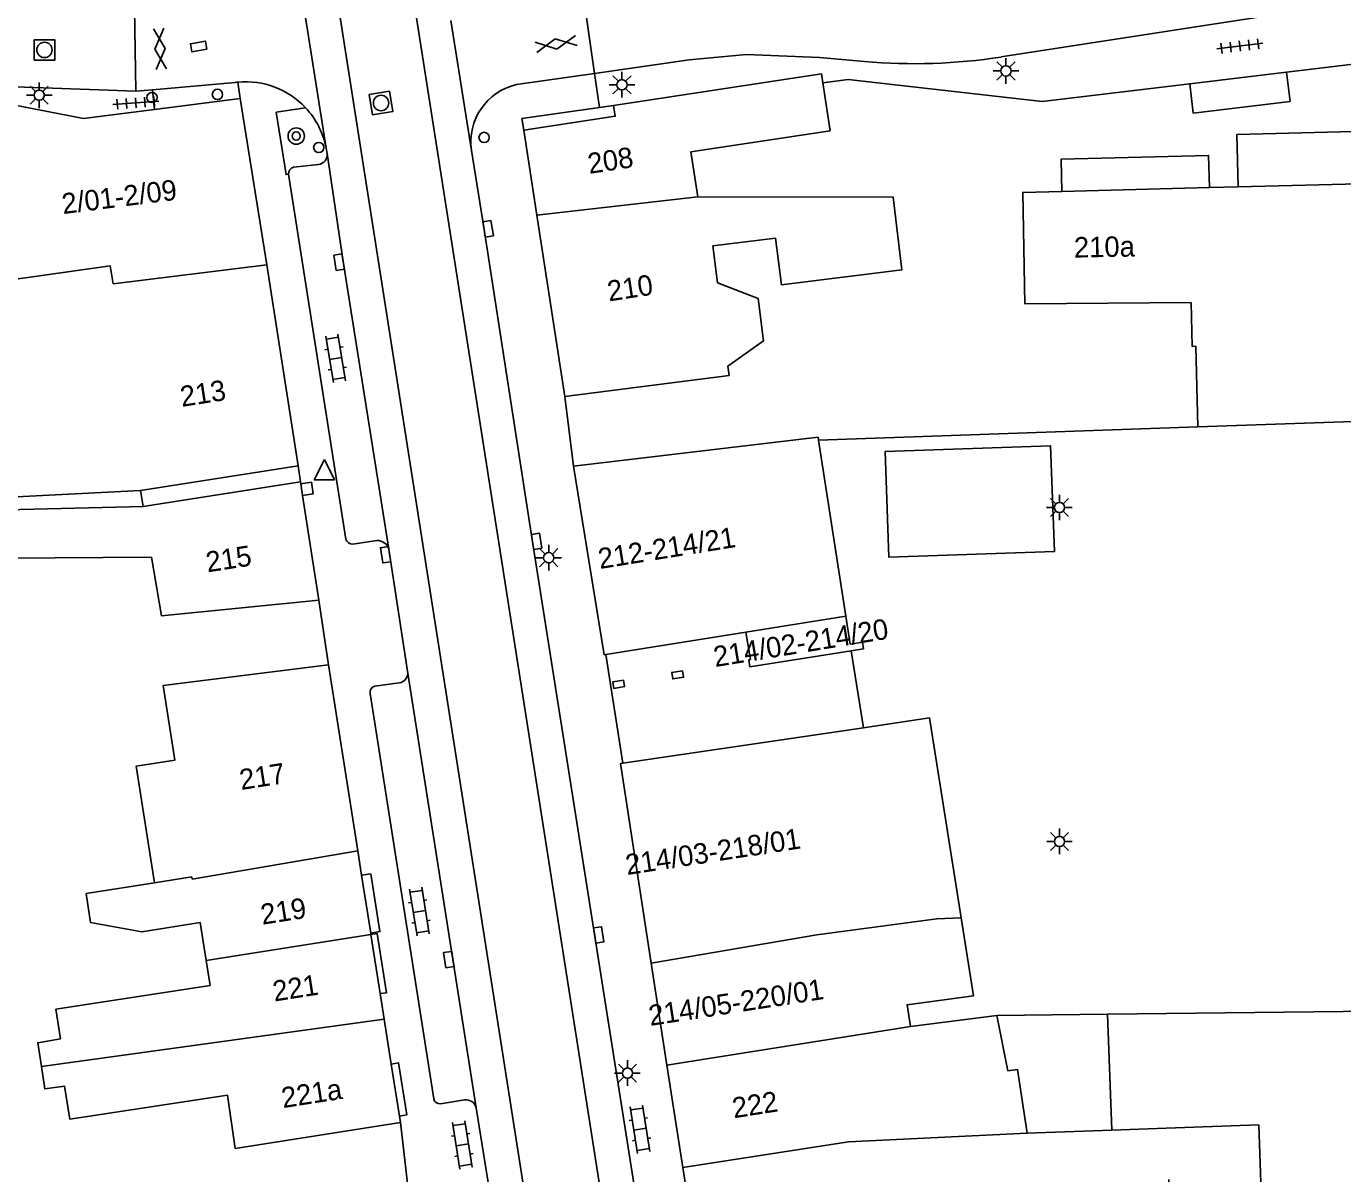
# Model space of a CAD drawing. Extents: x 132998 to 136004, y 396998 to 398512.
# Drawn here: x 133249 to 133313.3, y 397948.6 to 398004.6 of the extents above; entities that cross this region are included whole.
import ezdxf

# ---------------------------------------------------------------- set-up
doc = ezdxf.new("R2010")
doc.units = 0
for name, color, linetype in [('gg-afsc-muur', 7, 'Continuous'), ('gg-anno-huisnummerreeks BGT', 7, 'Continuous'), ('gg-bbg-gedigitaliseerde bebouwing', 7, 'Continuous'), ('gg-bbg-gedigitaliseerde bebouwing onder overbouw', 7, 'Continuous'), ('gg-bbg-gedigitaliseerde overbouw', 7, 'Continuous'), ('gg-bbg-hoofdgebouw', 7, 'Continuous'), ('gg-bbg-luifel en loopbrug', 7, 'Continuous'), ('gg-bbg-onder overbouw', 7, 'Continuous'), ('gg-bbg-overig bouwwerk', 7, 'Continuous'), ('gg-bbg-pand overbouw', 7, 'Continuous'), ('gg-bbg-pilaar onder overbouw', 7, 'Continuous'), ('gg-bbg-tussenscheiding', 7, 'Continuous'), ('gg-knt-verharding', 7, 'Continuous'), ('gg-knt-verharding nz', 7, 'Continuous'), ('gt-grn-weggrens', 7, 'Continuous'), ('gt-symb-boom', 7, 'Continuous'), ('gt-symb-drukknoppaal', 7, 'Continuous'), ('gt-symb-gesloten verharding', 7, 'Continuous'), ('gt-symb-klinker verharding', 7, 'Continuous'), ('gt-symb-kolk', 7, 'Continuous'), ('gt-symb-kolk center center', 7, 'Continuous'), ('gt-symb-lichtmast', 7, 'Continuous'), ('gt-symb-rioolschacht', 7, 'Continuous'), ('gt-symb-tegel verharding', 7, 'Continuous'), ('gt-symb-verkeersregelinstallatiepaal', 7, 'Continuous'), ('gt-symb-waterafsluiter', 7, 'Continuous')]:
    doc.layers.add(name, color=color, linetype=linetype)

# ---------------------------------------------------------------- blocks, each defined once
blk = doc.blocks.new('gt0-RS')
at = {"layer": 'gt-symb-rioolschacht'}
blk.add_lwpolyline([(-0.5, -0.5), (0.5, -0.5), (0.5, 0.5), (-0.5, 0.5)], close=True, dxfattribs=at)
blk.add_circle((0, 0), 0.375, dxfattribs=at)
blk = doc.blocks.new('gt0-GESVH1')
at = {"layer": 'gt-symb-gesloten verharding'}
for p, q in [((-0.992, -0.261), (0.008, 0.239)), ((0.008, -0.261), (-0.992, 0.239)), ((0.008, 0.239), (1.008, -0.261)), ((1.008, 0.239), (0.008, -0.261))]:
    blk.add_line(p, q, dxfattribs=at)
blk = doc.blocks.new('gt0-TEG1')
at = {"layer": 'gt-symb-tegel verharding'}
for p, q in [((-1.125, 0), (1.125, 0)), ((-0.9, -0.25), (-0.9, 0.25)), ((-0.45, -0.25), (-0.45, 0.25)), ((0, -0.25), (0, 0.25)), ((0.45, -0.25), (0.45, 0.25)), ((0.9, -0.25), (0.9, 0.25))]:
    blk.add_line(p, q, dxfattribs=at)
blk = doc.blocks.new('gt0-LMAST')
at = {"layer": 'gt-symb-lichtmast'}
for p, q in [((-0.182, 0.173), (-0.447, 0.438)), ((-0.005, 0.246), (-0.005, 0.621)), ((0.172, 0.173), (0.437, 0.438)), ((-0.255, -0.004), (-0.63, -0.004)), ((-0.182, -0.181), (-0.447, -0.446)), ((-0.005, -0.254), (-0.005, -0.629)), ((0.437, -0.446), (0.172, -0.181)), ((0.245, -0.004), (0.62, -0.004))]:
    blk.add_line(p, q, dxfattribs=at)
blk.add_circle((-0.005, -0.004), 0.25, dxfattribs=at)
blk = doc.blocks.new('gt0-KOLK')
at = {"layer": 'gt-symb-kolk'}
blk.add_lwpolyline([(0, 0), (0.375, 0), (0.375, 0.4), (-0.375, 0.4), (-0.375, 0), (0, 0)], dxfattribs=at)
blk = doc.blocks.new('gt0-KL1')
at = {"layer": 'gt-symb-klinker verharding'}
for p, q in [((-1.15, 0.3), (1.15, 0.3)), ((-1, -0.3), (-1, 0.3)), ((-0.5, 0.3), (-0.5, 0.45)), ((0, -0.3), (0, 0.3)), ((0.5, 0.3), (0.5, 0.45)), ((1, -0.3), (1, 0.3)), ((-1.15, -0.3), (1.15, -0.3)), ((-0.5, -0.45), (-0.5, -0.3)), ((0.5, -0.45), (0.5, -0.3))]:
    blk.add_line(p, q, dxfattribs=at)
blk = doc.blocks.new('gt0-WAFSL')
at = {"layer": 'gt-symb-waterafsluiter'}
for p, q in [((-0.5, -0.333), (0, 0.667)), ((0, 0.667), (0.5, -0.333)), ((0.5, -0.333), (-0.5, -0.333))]:
    blk.add_line(p, q, dxfattribs=at)
blk = doc.blocks.new('gt0-VIPAAL')
at = {"layer": 'gt-symb-verkeersregelinstallatiepaal'}
blk.add_circle((0, 0), 0.25, dxfattribs=at)
blk = doc.blocks.new('gt0-BOOM')
at = {"layer": 'gt-symb-boom'}
for radius in [0.4, 0.2]:
    blk.add_circle((0, 0), radius, dxfattribs=at)
blk = doc.blocks.new('gt0-KOLKCC')
at = {"layer": 'gt-symb-kolk center center'}
blk.add_lwpolyline([(-0.375, 0.2), (0.375, 0.2), (0.375, -0.2), (-0.375, -0.2)], close=True, dxfattribs=at)
blk = doc.blocks.new('gt0-DPAAL')
at = {"layer": 'gt-symb-drukknoppaal'}
blk.add_circle((0, 0), 0.25, dxfattribs=at)

msp = doc.modelspace()

# ---------------------------------------------------------------- linework, layer by layer
at = {"layer": 'gg-afsc-muur'}
for p, q in [((133310.547, 398002.362), (133314.62, 398002.851)), ((133306.217, 397985.057), (133287.694, 397984.412)), ((133319.735, 397956.616), (133301.812, 397956.397))]:
    msp.add_line(p, q, dxfattribs=at)
msp.add_lwpolyline([(133287.915, 398001.851), (133289.14, 398002.001), (133298.62, 398000.931), (133305.823, 398001.795)], dxfattribs=at)
at = {"layer": 'gg-bbg-gedigitaliseerde bebouwing'}
for p, q in [((133238.066, 397981.119), (133254.599, 397981.955)), ((133248.053, 397981.01), (133254.722, 397981.169)), ((133297.882, 397950.596), (133302.013, 397950.743)), ((133302.013, 397950.743), (133304.675, 397950.837))]:
    msp.add_line(p, q, dxfattribs=at)
for points in [[(133281.81, 397996.285), (133281.467, 397998.477), (133288.27, 397999.51)], [(133285.883, 397991.993), (133291.766, 397992.724), (133291.343, 397996.263), (133281.81, 397996.285)], [(133263.31, 397976.6), (133255.618, 397975.843), (133255.14, 397978.696), (133248.078, 397978.649), (133248.053, 397981.01)], [(133263.78, 397973.45), (133255.697, 397972.447), (133256.074, 397970.051)], [(133256.074, 397970.051), (133256.272, 397968.793), (133254.378, 397968.495), (133255.274, 397962.81)], [(133254.669, 397960.421), (133252.163, 397960.882), (133251.942, 397962.287), (133255.274, 397962.81)], [(133257.805, 397959.028), (133257.516, 397960.868), (133254.669, 397960.421)], [(133249.76, 397953.846), (133249.583, 397955.006), (133250.685, 397955.197), (133250.463, 397956.64), (133257.997, 397957.803), (133257.805, 397959.028)], [(133297.882, 397950.596), (133297.414, 397953.702), (133296.947, 397953.632), (133296.41, 397956.331)], [(133267.29, 397951.11), (133259.225, 397949.855), (133258.846, 397952.444), (133251.147, 397951.284), (133250.893, 397952.888), (133249.926, 397952.755), (133249.76, 397953.846)], [(133304.675, 397950.837), (133309.191, 397950.998), (133309.324, 397947.268), (133304.843, 397947.108), (133304.799, 397948.341)]]:
    msp.add_lwpolyline(points, dxfattribs=at)
at = {"layer": 'gg-bbg-gedigitaliseerde bebouwing onder overbouw'}
for p, q in [((133262.287, 397983.156), (133254.599, 397981.955)), ((133254.722, 397981.169), (133262.409, 397982.37))]:
    msp.add_line(p, q, dxfattribs=at)
at = {"layer": 'gg-bbg-gedigitaliseerde overbouw'}
msp.add_line((133254.722, 397981.169), (133254.599, 397981.955), dxfattribs=at)
at = {"layer": 'gg-bbg-hoofdgebouw'}
for p, q in [((133287.915, 398001.851), (133288.27, 397999.51)), ((133259.455, 398001.074), (133255.281, 398000.542)), ((133260.768, 397992.966), (133259.455, 398001.074)), ((133273.95, 397995.384), (133273.31, 397999.53)), ((133299.58, 397996.55), (133306.778, 397996.736)), ((133306.778, 397996.736), (133308.191, 397996.772)), ((133308.191, 397996.772), (133315.45, 397996.96)), ((133275.315, 397986.545), (133273.95, 397995.384)), ((133262.287, 397983.156), (133260.768, 397992.966)), ((133306.217, 397985.057), (133317.351, 397985.444)), ((133289.026, 397975.816), (133287.694, 397984.412)), ((133262.423, 397982.282), (133262.409, 397982.37)), ((133262.512, 397981.71), (133262.423, 397982.282)), ((133263.31, 397976.6), (133262.512, 397981.71)), ((133289.236, 397974.461), (133289.026, 397975.816)), ((133263.78, 397973.45), (133265.206, 397964.371)), ((133265.206, 397964.371), (133265.393, 397963.183)), ((133265.393, 397963.183), (133265.837, 397960.357)), ((133265.837, 397960.357), (133265.847, 397960.292)), ((133265.847, 397960.292), (133265.848, 397960.288)), ((133265.848, 397960.288), (133266.301, 397957.403)), ((133279.524, 397958.887), (133280.292, 397953.914)), ((133266.301, 397957.403), (133266.496, 397956.164)), ((133292.19, 397955.797), (133296.41, 397956.331)), ((133266.496, 397956.164), (133266.841, 397953.965)), ((133266.841, 397953.965), (133267.24, 397951.426)), ((133280.292, 397953.914), (133281.072, 397948.926)), ((133267.24, 397951.426), (133267.29, 397951.11)), ((133281.072, 397948.926), (133282.056, 397942.566))]:
    msp.add_line(p, q, dxfattribs=at)
for points in [[(133287.915, 398001.851), (133287.85, 398002.281), (133277.69, 398000.741)], [(133255.281, 398000.542), (133251.821, 398000.101), (133246.681, 398001.094), (133246.587, 398001.061)], [(133273.31, 397999.53), (133277.77, 398000.211), (133277.69, 398000.741)], [(133305.892, 397991.125), (133297.772, 397991.059), (133297.67, 397996.501), (133299.58, 397996.55)], [(133285.883, 397991.993), (133285.601, 397994.266), (133282.544, 397993.886), (133282.767, 397992.09), (133284.747, 397991.318), (133285.004, 397989.254), (133283.271, 397988.021), (133283.329, 397987.565), (133275.315, 397986.545)], [(133306.217, 397985.057), (133306.125, 397988.99), (133305.932, 397988.986), (133305.892, 397991.125)], [(133287.694, 397984.412), (133287.672, 397984.555), (133275.74, 397983.135)], [(133275.74, 397983.135), (133277.233, 397973.94), (133277.32, 397973.954)], [(133289.287, 397974.131), (133289.893, 397974.23), (133289.842, 397974.555), (133289.236, 397974.461)], [(133289.893, 397970.377), (133293.117, 397970.856), (133294.66, 397961.098)], [(133279.524, 397958.887), (133278.027, 397968.626), (133278.137, 397968.642)], [(133294.66, 397961.098), (133295.261, 397957.294), (133292.021, 397956.863), (133292.19, 397955.797)]]:
    msp.add_lwpolyline(points, dxfattribs=at)
at = {"layer": 'gg-bbg-luifel en loopbrug'}
for p, q in [((133305.823, 398001.795), (133310.547, 398002.362)), ((133301.812, 397956.397), (133296.41, 397956.331)), ((133302.013, 397950.743), (133301.812, 397956.397))]:
    msp.add_line(p, q, dxfattribs=at)
for points in [[(133305.823, 398001.795), (133305.995, 398000.363), (133310.719, 398000.93), (133310.547, 398002.362)], [(133315.092, 397999.503), (133308.125, 397999.323), (133308.191, 397996.772)], [(133306.778, 397996.736), (133306.737, 397998.306), (133299.539, 397998.12), (133299.58, 397996.55)]]:
    msp.add_lwpolyline(points, dxfattribs=at)
at = {"layer": 'gg-bbg-onder overbouw'}
for p, q in [((133277.32, 397973.954), (133284.153, 397975.037)), ((133278.137, 397968.642), (133289.893, 397970.377))]:
    msp.add_line(p, q, dxfattribs=at)
msp.add_lwpolyline([(133289.287, 397974.131), (133284.348, 397973.35), (133284.289, 397973.691), (133284.371, 397973.704), (133284.153, 397975.037)], dxfattribs=at)
at = {"layer": 'gg-bbg-overig bouwwerk'}
msp.add_lwpolyline([(133299.21, 397978.985), (133299.03, 397984.135), (133290.943, 397983.853), (133291.122, 397978.703), (133299.21, 397978.985)], dxfattribs=at)
at = {"layer": 'gg-bbg-pand overbouw'}
for p, q in [((133262.409, 397982.37), (133262.287, 397983.156)), ((133278.137, 397968.642), (133277.32, 397973.954)), ((133289.287, 397974.131), (133289.893, 397970.377))]:
    msp.add_line(p, q, dxfattribs=at)
at = {"layer": 'gg-bbg-pilaar onder overbouw'}
for points in [[(133281.056, 397973.158), (133281.107, 397972.842), (133280.578, 397972.758), (133280.528, 397973.074), (133281.056, 397973.158)], [(133278.176, 397972.699), (133278.226, 397972.383), (133277.698, 397972.299), (133277.648, 397972.615), (133278.176, 397972.699)]]:
    msp.add_lwpolyline(points, dxfattribs=at)
at = {"layer": 'gg-bbg-tussenscheiding'}
for p, q in [((133273.95, 397995.384), (133281.81, 397996.285)), ((133289.026, 397975.816), (133284.153, 397975.037)), ((133257.805, 397959.028), (133265.847, 397960.292)), ((133266.496, 397956.164), (133249.76, 397953.846)), ((133292.19, 397955.797), (133280.292, 397953.914)), ((133289.161, 397950.168), (133297.882, 397950.596)), ((133281.072, 397948.926), (133289.161, 397950.168))]:
    msp.add_line(p, q, dxfattribs=at)
for points in [[(133246.309, 397991.958), (133253.123, 397992.909), (133253.266, 397992.042), (133260.768, 397992.966)], [(133255.274, 397962.81), (133257.102, 397963.097), (133257.122, 397962.99), (133265.206, 397964.371)], [(133279.524, 397958.887), (133287.61, 397960.271), (133293.474, 397961.05), (133294.66, 397961.098)]]:
    msp.add_lwpolyline(points, dxfattribs=at)
at = {"layer": 'gg-knt-verharding'}
for p, q in [((133254.368, 398001.438), (133254.311, 398005.481)), ((133276.343, 398005.263), (133276.764, 398002.307)), ((133313.286, 398005.687), (133296.62, 398003.106)), ((133259.217, 398001.862), (133255.186, 398001.51)), ((133276.764, 398002.307), (133272.96, 398001.759)), ((133276.764, 398002.307), (133277.003, 398000.642)), ((133254.368, 398001.438), (133246.48, 398001.73)), ((133255.186, 398001.51), (133254.368, 398001.438)), ((133255.281, 398000.542), (133255.186, 398001.51)), ((133277.69, 398000.741), (133277.003, 398000.642)), ((133263.661, 397998.652), (133263.702, 397998.396)), ((133264.621, 397979.582), (133261.827, 397997.391)), ((133263.286, 397997.859), (133262.066, 397997.725)), ((133275.74, 397983.135), (133275.315, 397986.545)), ((133266.129, 397979.507), (133264.955, 397979.333)), ((133267.639, 397973.132), (133266.721, 397979.094)), ((133263.31, 397976.6), (133263.78, 397973.45)), ((133270.991, 397951.832), (133267.639, 397973.132)), ((133266.032, 397972.404), (133267.219, 397972.561)), ((133268.909, 397952.267), (133265.805, 397972.056)), ((133265.844, 397963.254), (133265.393, 397963.183)), ((133270.41, 397952.222), (133269.244, 397952.032)), ((133271.574, 397948.182), (133270.991, 397951.832)), ((133267.29, 397951.11), (133267.68, 397947.72))]:
    msp.add_line(p, q, dxfattribs=at)
for points in [[(133289.935, 398002.887), (133287.74, 398003.081), (133284.18, 398003.221), (133281.39, 398002.97), (133276.764, 398002.307)], [(133262.652, 398000.633), (133261.227, 398000.411), (133261.701, 397997.371), (133261.827, 397997.391)], [(133277.003, 398000.642), (133273.22, 398000.1), (133273.31, 397999.53)], [(133266.721, 397979.094), (133264.492, 397993.125), (133263.702, 397998.396)], [(133270.752, 397998.537), (133271.369, 397994.688), (133273.736, 397979.442), (133279.182, 397944.946), (133282.845, 397921.574), (133283.086, 397920.549), (133283.652, 397918.633), (133283.869, 397917.647), (133284.148, 397915.884), (133284.319, 397914.688), (133284.372, 397913.698), (133284.356, 397912.685), (133284.411, 397911.685), (133286.46, 397898.583), (133288.435, 397886.269)], [(133262.512, 397981.71), (133263.025, 397981.79), (133262.941, 397982.362), (133262.423, 397982.282)], [(133265.837, 397960.357), (133266.288, 397960.428), (133265.844, 397963.254)], [(133266.301, 397957.403), (133266.607, 397957.451), (133266.154, 397960.336), (133265.848, 397960.288)], [(133267.24, 397951.426), (133267.596, 397951.482), (133267.197, 397954.021), (133266.841, 397953.965)]]:
    msp.add_lwpolyline(points, dxfattribs=at)
for centre, radius, start, end in [((133292.377, 398030.482), 27.703, 264.94261, 278.81005), ((133259.595, 397999.059), 2.829, 94.90813, 97.67977), ((133259.737, 397997.898), 3.997, 43.17197, 95.50672), ((133273.596, 397998.956), 2.875, 102.78205, 188.37315), ((133259.735, 397997.9), 3.998, 10.84754, 43.13547), ((133263.228, 397998.334), 0.478, 276.99717, 7.47479), ((133262.136, 397997.422), 0.311, 103.01266, 185.81468), ((133264.937, 397979.657), 0.325, 193.3959, 273.19438), ((133266.173, 397978.94), 0.569, 15.73048, 94.46755), ((133267.133, 397973.064), 0.51, 279.69203, 7.63516), ((133266.111, 397972.105), 0.31, 104.74751, 189.01976), ((133269.204, 397952.331), 0.301, 192.19709, 277.70416), ((133270.476, 397951.693), 0.533, 15.10123, 97.15529)]:
    msp.add_arc(centre, radius, start, end, dxfattribs=at)
at = {"layer": 'gg-knt-verharding nz'}
for p, q in [((133263.661, 397998.652), (133262.596, 398005.34)), ((133269.746, 398004.892), (133270.752, 397998.537))]:
    msp.add_line(p, q, dxfattribs=at)
for points in [[(133277.747, 397917.384), (133277.648, 397920.214), (133263.686, 398009.189)], [(133267.639, 398007.833), (133281.311, 397920.598), (133282.086, 397918.057)]]:
    msp.add_lwpolyline(points, dxfattribs=at)
at = {"layer": 'gt-grn-weggrens'}
msp.add_line((133259.455, 398001.074), (133259.353, 398001.877), dxfattribs=at)

# ---------------------------------------------------------------- block references
at = {"layer": 'gt-symb-boom'}
msp.add_blockref('gt0-BOOM', (133262.198, 397999.249), dxfattribs=at)
at = {"layer": 'gt-symb-drukknoppaal', "rotation": -81.26733497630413}
msp.add_blockref('gt0-DPAAL', (133255.159, 398001.13), dxfattribs=at)
at = {"layer": 'gt-symb-gesloten verharding'}
for p, rotation in [((133255.556, 398003.511), -86.27357411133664), ((133274.875, 398003.75), 9.50001059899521)]:
    msp.add_blockref('gt0-GESVH1', p, dxfattribs=dict(at, rotation=rotation))
at = {"layer": 'gt-symb-klinker verharding'}
for p, rotation in [((133264.124, 397988.4), -80.8486039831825), ((133268.211, 397961.408), -80.8486039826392), ((133278.982, 397950.787), -81.1405706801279), ((133270.308, 397950.022), -81.1405706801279)]:
    msp.add_blockref('gt0-KL1', p, dxfattribs=dict(at, rotation=rotation))
at = {"layer": 'gt-symb-kolk'}
for p, rotation in [((133271.369, 397994.688), -80.8998426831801), ((133264.492, 397993.125), 99.0271660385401), ((133273.736, 397979.442), -81.17714564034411), ((133266.758, 397978.851), 98.75781984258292), ((133276.77, 397960.238), -81.02191948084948), ((133269.846, 397959.097), 98.95416603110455)]:
    msp.add_blockref('gt0-KOLK', p, dxfattribs=dict(at, rotation=rotation))
at = {"layer": 'gt-symb-kolk center center', "rotation": -169.7283567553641}
msp.add_blockref('gt0-KOLKCC', (133257.436, 398003.622), dxfattribs=at)
at = {"layer": 'gt-symb-lichtmast'}
for p in [(133296.853, 398002.429), (133249.657, 398001.246), (133278.107, 398001.756), (133299.463, 397981.129), (133274.53, 397978.679), (133299.467, 397964.833), (133278.375, 397953.531)]:
    msp.add_blockref('gt0-LMAST', p, dxfattribs=at)
at = {"layer": 'gt-symb-rioolschacht'}
msp.add_blockref('gt0-RS', (133249.908, 398003.45), dxfattribs=at)
at = {"layer": 'gt-symb-rioolschacht', "rotation": -80.98877455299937}
msp.add_blockref('gt0-RS', (133266.339, 398000.861), dxfattribs=at)
at = {"layer": 'gt-symb-tegel verharding'}
for p, rotation in [((133308.265, 398003.641), 6.890548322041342), ((133254.365, 398000.87), 4.244862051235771)]:
    msp.add_blockref('gt0-TEG1', p, dxfattribs=dict(at, rotation=rotation))
at = {"layer": 'gt-symb-verkeersregelinstallatiepaal'}
for p, rotation in [((133258.352, 398001.282), -81.26733497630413), ((133271.37, 397999.183), -81.26733497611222)]:
    msp.add_blockref('gt0-VIPAAL', p, dxfattribs=dict(at, rotation=rotation))
msp.add_blockref('gt0-VIPAAL', (133263.298, 397998.688), dxfattribs=at)
at = {"layer": 'gt-symb-waterafsluiter'}
msp.add_blockref('gt0-WAFSL', (133263.572, 397982.805), dxfattribs=at)

# ---------------------------------------------------------------- texts
at = {"layer": 'gg-anno-huisnummerreeks BGT'}
for s, rotation, p in [('208', 8.8, (133276.508, 397997.399)), ('2/01-2/09', 7.2, (133250.817, 397995.44)), ('210a', 1.1, (133300.175, 397993.316)), ('210', 8.8, (133277.468, 397991.176)), ('213', 8.8, (133256.615, 397986.032)), ('212-214/21', 9.2, (133277.026, 397978.12)), ('215', 8.9, (133257.87, 397977.956)), ('214/02-214/20', 9.3, (133282.655, 397973.336)), ('217', 8.9, (133259.511, 397967.338)), ('214/03-218/01', 8.7, (133278.351, 397963.189)), ('219', 8.9, (133260.544, 397960.763)), ('221', 8.9, (133261.133, 397957.017)), ('214/05-220/01', 8.8, (133279.485, 397955.828)), ('221a', 8.9, (133261.557, 397951.816)), ('222', 8.9, (133283.567, 397951.32))]:
    msp.add_text(s, height=1, rotation=rotation, dxfattribs=at).set_placement(p)

doc.saveas('drawing.dxf')
